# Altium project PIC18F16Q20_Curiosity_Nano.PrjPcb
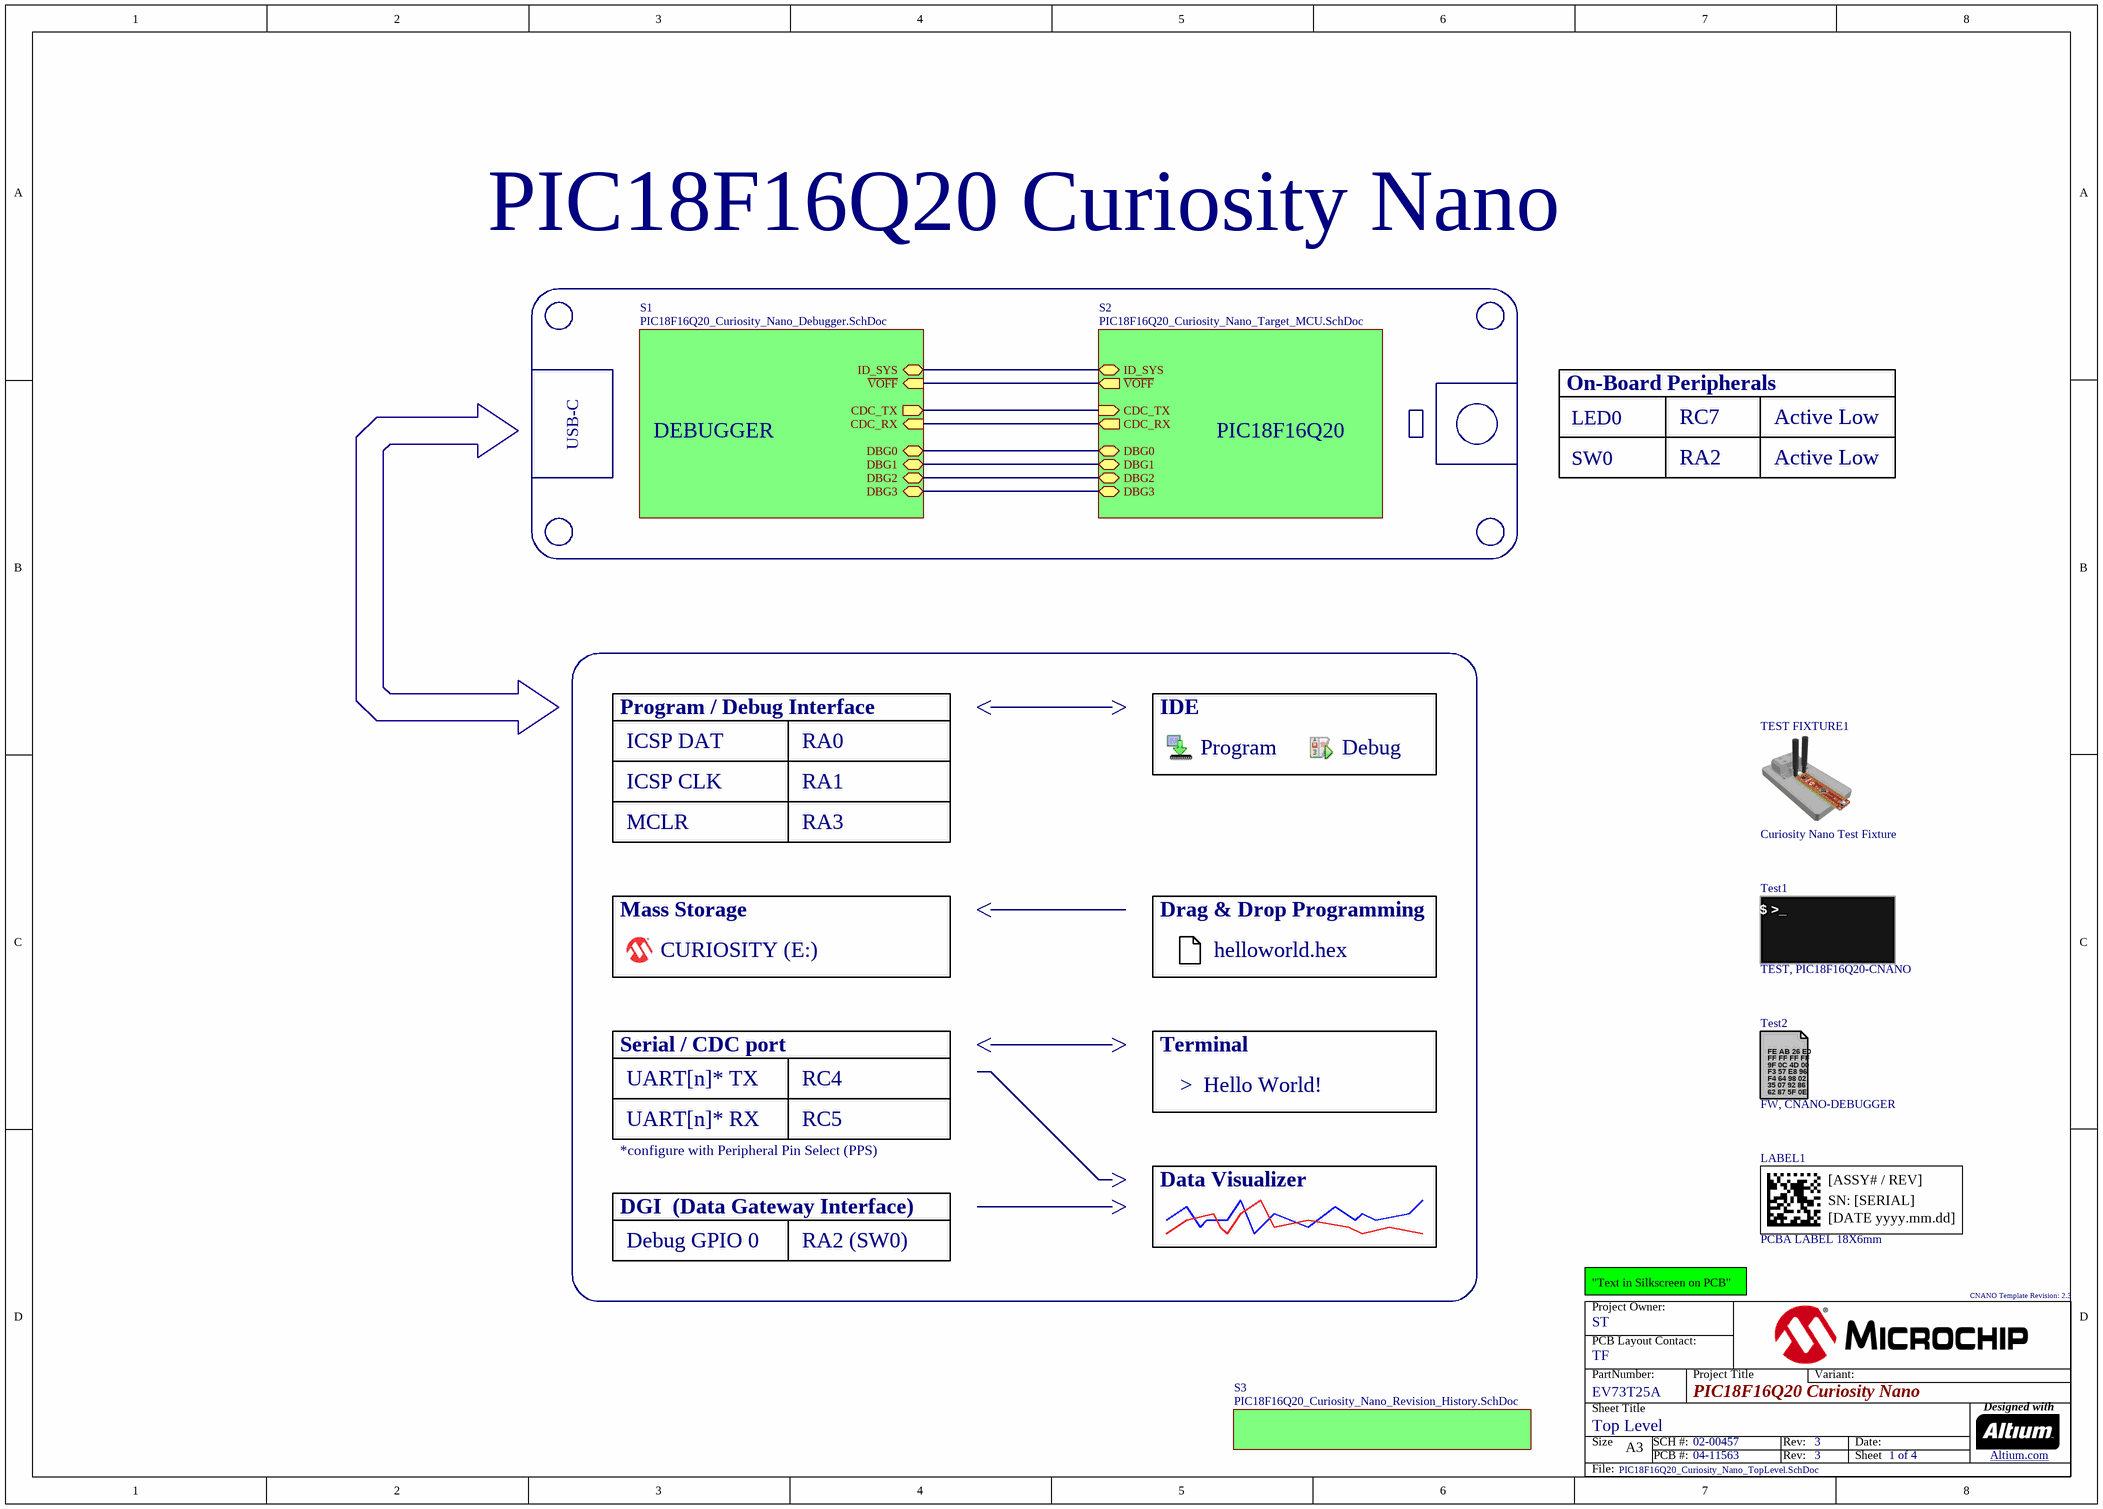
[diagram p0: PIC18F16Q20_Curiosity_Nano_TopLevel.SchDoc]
CNANO_Template_Revision: 2.3; ProjectContactOwner: ST; ProjectContactPCB: TF; ProjectContactPCBEmail: terje.frostad@microchip.com; ProjectPartNumber: EV73T25A; ProjectPCBAssyNumber: 02-00457; ProjectPCBAssyRevision: 3; ProjectPCBFabNumber: 04-11563; ProjectPCBFabRevision: 3; ProjectTargetName: PIC18F16Q20; ProjectTitle: PIC18F16Q20 Curiosity Nano
4 sheets, 80 parts. Net scope: hierarchical (ports join the sheet entries above them; power ports are global).
Board file: PIC18F16Q20_Curiosity_Nano.PcbDoc
Sheets:
  PIC18F16Q20_Curiosity_Nano_TopLevel.SchDoc
    S2 = PIC18F16Q20_Curiosity_Nano_Target_MCU.SchDoc
    S1 = PIC18F16Q20_Curiosity_Nano_Debugger.SchDoc
    S3 = PIC18F16Q20_Curiosity_Nano_Revision_History.SchDoc

## Sheet PIC18F16Q20_Curiosity_Nano_TopLevel.SchDoc
size A3; SheetTitle: Top Level; CompanyName: Microchip Technology Inc.; Organization: Microchip Technology; Address1: 2355 West Chandler Blvd.; Address2: Chandler, AZ  85224; Address4: USA; SheetNumber: 1; SheetTotal: 4

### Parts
LABEL1  value PCBA LABEL 18X6mm  [08-10015]  (hidden comment: 08-10015)
Test1  Description_: TEST, PIC18F16Q20-CNANO  (hidden comment: Mechanical)  (mechanical)
Test2  Description_: FW, CNANO-DEBUGGER  (hidden comment: Mechanical)  (mechanical)
TEST_FIXTURE1  value Curiosity Nano Test Fixture  (hidden comment: Jupiter Test Jig)  (mechanical)

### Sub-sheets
S1 = PIC18F16Q20_Curiosity_Nano_Debugger.SchDoc: DBG2 (bidir), DBG1 (bidir), DBG3 (bidir), DBG0 (bidir), ~{VOFF} (in), ID_SYS (bidir), CDC_RX (in), CDC_TX (out)
S2 = PIC18F16Q20_Curiosity_Nano_Target_MCU.SchDoc: DBG0 (bidir), DBG1 (bidir), DBG3 (bidir), DBG2 (bidir), ~{VOFF} (out), ID_SYS (bidir), CDC_RX (out), CDC_TX (in)
S3 = PIC18F16Q20_Curiosity_Nano_Revision_History.SchDoc: no entries

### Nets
CDC_RX: sheet S2/CDC_RX, sheet S1/CDC_RX
CDC_TX: sheet S2/CDC_TX, sheet S1/CDC_TX
DBG0: sheet S2/DBG0, sheet S1/DBG0
DBG1: sheet S2/DBG1, sheet S1/DBG1
DBG2: sheet S2/DBG2, sheet S1/DBG2
DBG3: sheet S2/DBG3, sheet S1/DBG3
ID_SYS: sheet S2/ID_SYS, sheet S1/ID_SYS
~{VOFF}: sheet S2/~{VOFF}, sheet S1/~{VOFF}

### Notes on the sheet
- USB-C
- DEBUGGER
- On-Board Peripherals
- LED0
- RC7
- Active Low
- SW0
- RA2
- Program / Debug Interface
- IDE
- ICSP DAT
- RA0
- Program
- Debug
- ICSP CLK
- MCLR
- RA1
- RA3
- Mass Storage
- Drag & Drop Programming
- CURIOSITY (E:)
- helloworld.hex
- Serial / CDC port
- Terminal
- UART[n]* TX
- UART[n]* RX
- RC5
- RC4
- >  Hello World!
- *configure with Peripheral Pin Select (PPS)
- Data Visualizer
- DGI  (Data Gateway Interface)
- Debug GPIO 0
- RA2 (SW0)
- "Text in Silkscreen on PCB"

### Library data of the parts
LABEL1 = 08-10015: Manufacturer 1: ACT Logimark AS; Manufacturer Part Number 1: 505462; Description_: LABEL PCBA 18x6mm Datamatrix Assy# / Rev / Serial / Date; Populated: MECH
Test1 = 13-00211: Populated: Yes
Test2 = 13-00018: Populated: Yes; Value: Debugger Firmware
TEST_FIXTURE1 = 15-00009: Manufacturer 1: Raynen; Manufacturer Part Number 1: MCHP 15-00009; Populated: YES

## Sheet PIC18F16Q20_Curiosity_Nano_Target_MCU.SchDoc
size A3; SheetTitle: Target MCU; CompanyName: Microchip Technology Inc.; Organization: Microchip Technology; Address1: 2355 West Chandler Blvd.; Address2: Chandler, AZ  85224; Address4: USA; SheetNumber: 2; SheetTotal: 4
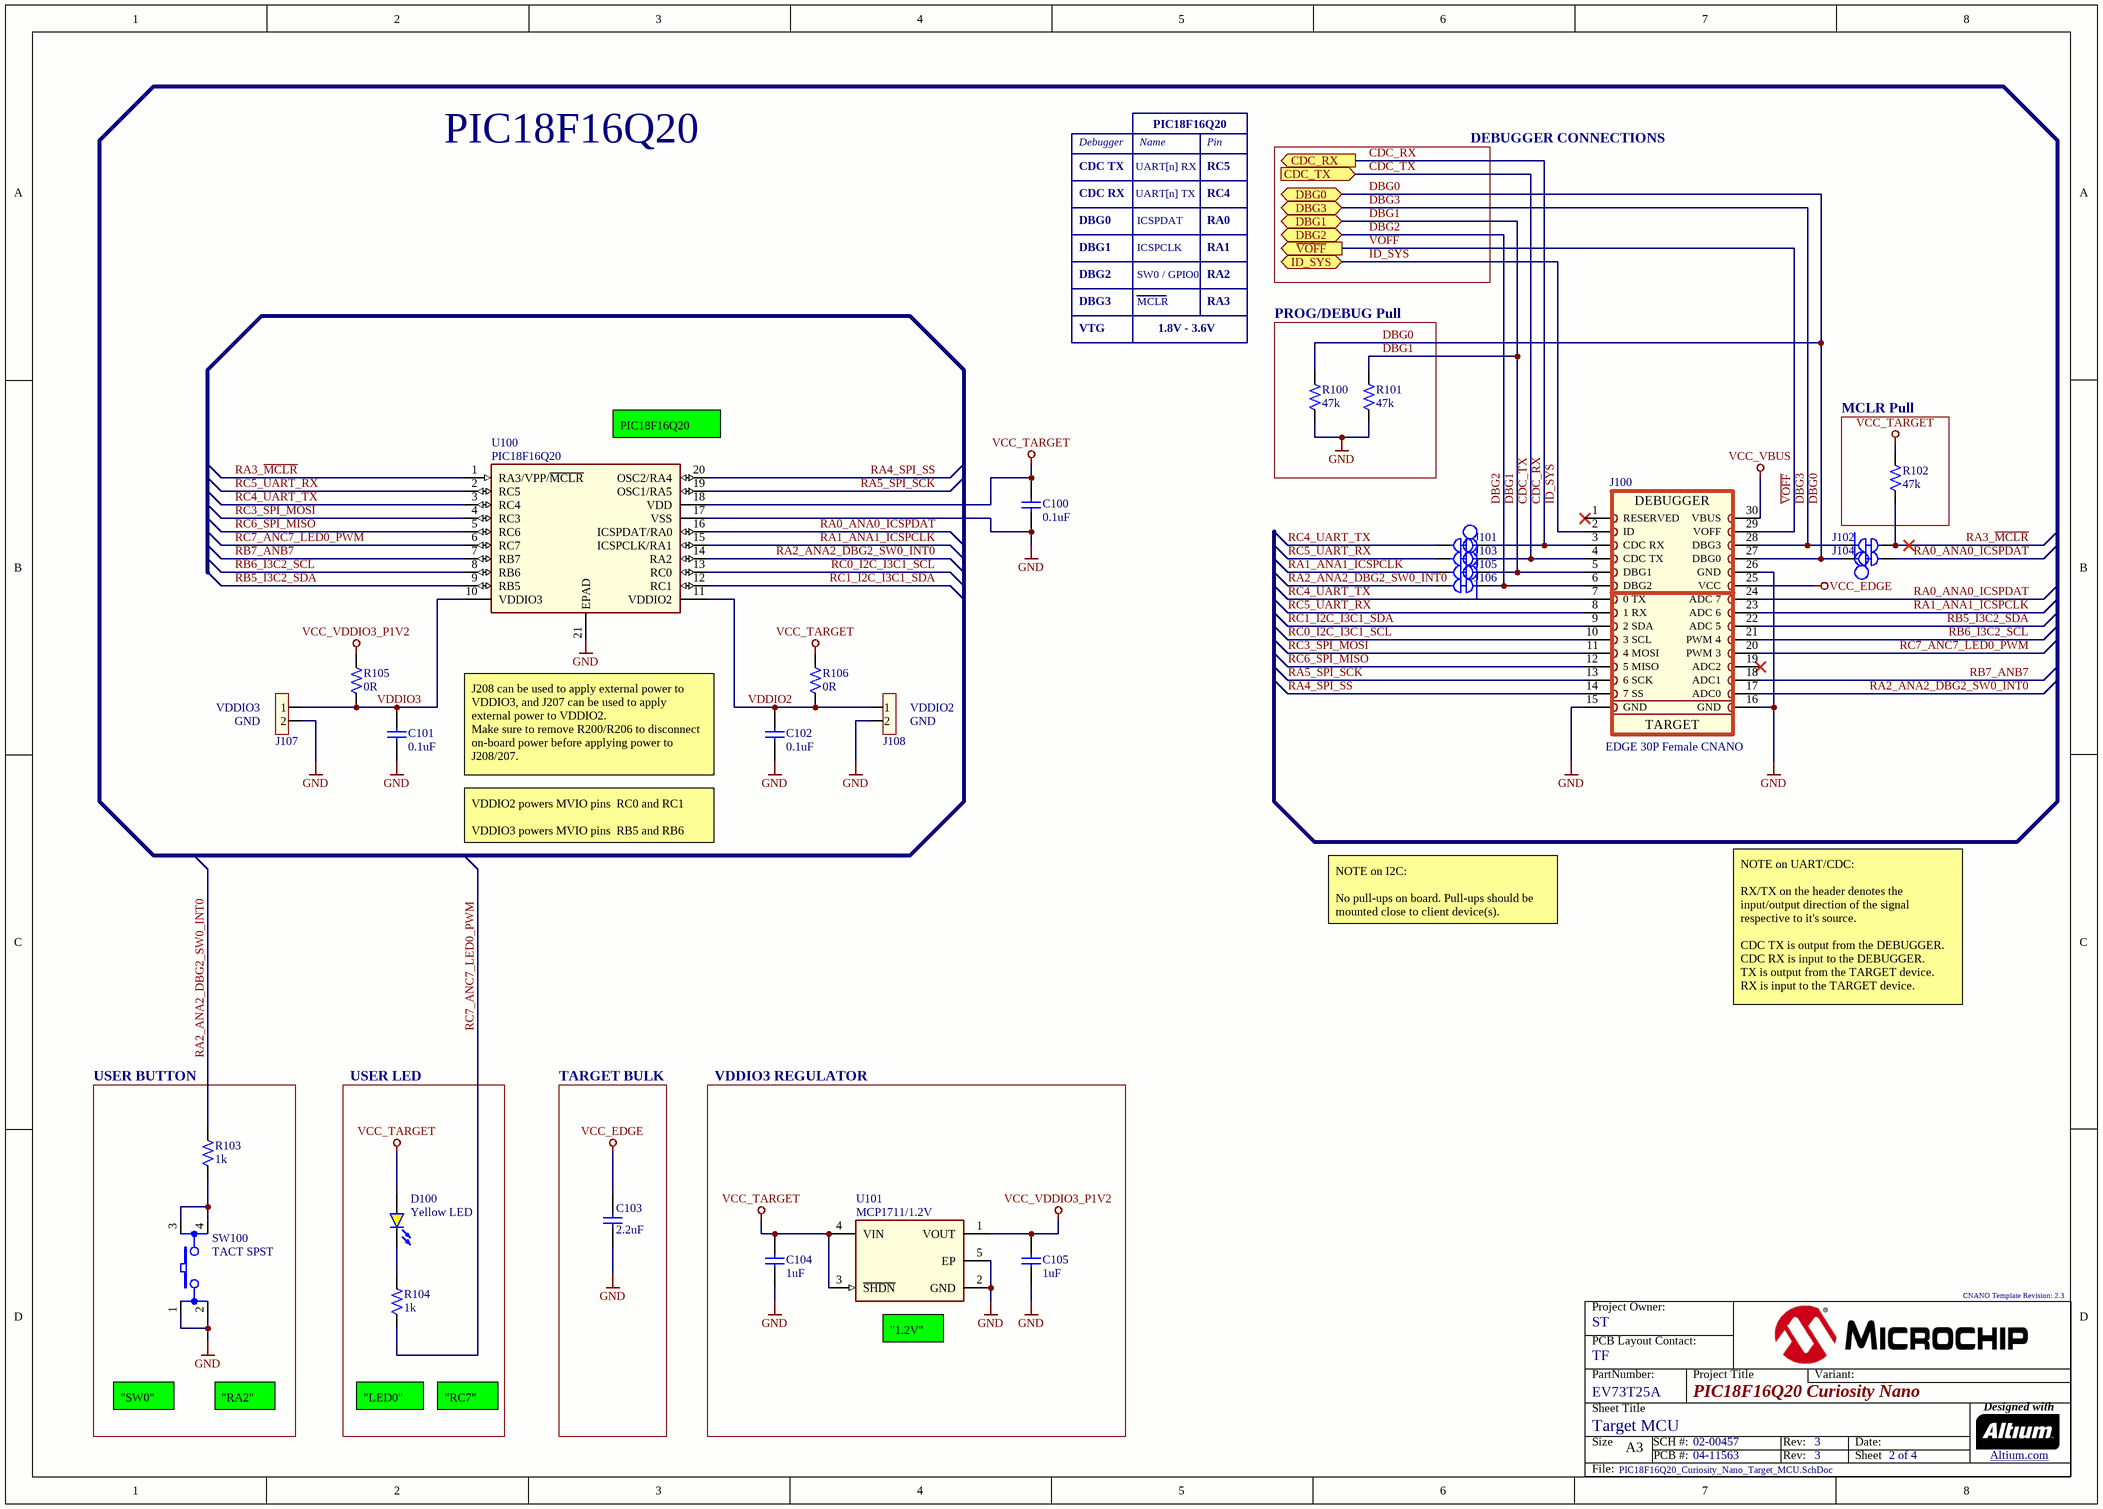
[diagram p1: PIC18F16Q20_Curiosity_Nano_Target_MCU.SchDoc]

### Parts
C100  value 0.1uF  [CAP_C_0402]  (hidden comment: Capacitor NP)
C101  value 0.1uF  [CAP_C_0402]  (hidden comment: Capacitor NP)
C102  value 0.1uF  [CAP_C_0402]  (hidden comment: Capacitor NP)
C103  value 2.2uF  [CAP_C_0402]  (hidden comment: Capacitor NP)
C104  value 1uF  [CAP_C_0402]  (hidden comment: Capacitor NP)
C105  value 1uF  [CAP_C_0402]  (hidden comment: Capacitor NP)
D100  value Yellow LED  [LED_0603_Yellow]  (hidden comment: LED_yellow)
J100  value EDGE 30P Female CNANO  [CON_EDGE_CNANO-30]  (hidden comment: CON EDGE CNANO-30)  (no BOM)
J101  CON JMPR LINK CLOSED  [CON_JMPR_0402_PCB_TRACE_LINK_0.9mm_PAD_0.6mm_PTH]  (value not drawn)  (net tie, no BOM)
J102  CON JMPR LINK CLOSED  [CON_JMPR_0402_PCB_TRACE_LINK_0.9mm_PAD_0.6mm_PTH]  (value not drawn)  (net tie, no BOM)
J103  CON JMPR LINK CLOSED  [CON_JMPR_0402_PCB_TRACE_LINK_0.9mm_PAD_0.6mm_PTH]  (value not drawn)  (net tie, no BOM)
J104  CON JMPR LINK CLOSED  [CON_JMPR_0402_PCB_TRACE_LINK_0.9mm_PAD_0.6mm_PTH]  (value not drawn)  (net tie, no BOM)
J105  CON JMPR LINK CLOSED  [CON_JMPR_0402_PCB_TRACE_LINK_0.9mm_PAD_0.6mm_PTH]  (value not drawn)  (net tie, no BOM)
J106  CON JMPR LINK CLOSED  [CON_JMPR_0402_PCB_TRACE_LINK_0.9mm_PAD_0.6mm_PTH]  (value not drawn)  (net tie, no BOM)
J107  Header 1x2  [HDR_M_2.54_1x2]  (value not drawn)
J108  Header 1x2  [HDR_M_2.54_1x2]  (value not drawn)
R100  value 47k  [RES_C_0402]  (hidden comment: Resistor)
R101  value 47k  [RES_C_0402]  (hidden comment: Resistor)
R102  value 47k  [RES_C_0402]  (hidden comment: Resistor)
R103  value 1k  [RES_C_0402]  (hidden comment: Resistor)
R104  value 1k  [RES_C_0402]  (hidden comment: Resistor)
R105  value 0R  [RES_C_0402]  (hidden comment: Resistor)
R106  value 0R  [RES_C_0402]  (hidden comment: Resistor)
SW100  value TACT SPST  [SW_TACT_SMD_KLS_L-KLS7-TS0304A-2-300-T]  (hidden comment: Switch 4 Pin)
U100  value PIC18F16Q20  [VQFN-20_3X3_EP1.8x1.8]  (hidden comment: PIC18F16Q20 T-I/REB)
U101  value MCP1711/1.2V  [UQFN-4_1x1_EP0.48x0.48]  (hidden comment: MCP1711 UQFN-4)

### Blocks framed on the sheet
PROG/DEBUG Pull: R100 R101
MCLR Pull: R102
USER BUTTON: R103 SW100
USER LED: D100 R104
TARGET BULK: C103
VDDIO3 REGULATOR: C104 C105 U101

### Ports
CDC_RX (out), CDC_TX (in), DBG0 (bidir), DBG1 (bidir), DBG2 (bidir), DBG3 (bidir), ID_SYS (bidir), ~{VOFF} (out)

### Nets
GND: C100.2 C101.2 C102.2 C103.1 C104.1 C105.1 J100.15(GND) J100.16(GND) J100.26(GND) J107.2 J108.2 R100.2 R101.2 SW100.1 SW100.2 U100.17(VSS) U100.21(EPAD) U101.2(GND) U101.5(EP)
VCC_EDGE: C103.2 J100.25(VCC)
VCC_TARGET: C100.1 C104.2 D100.1(A) R102.2 R106.2 U100.18(VDD) U101.3(~{SHDN}) U101.4(VIN)
VCC_VBUS: J100.30(VBUS)
VCC_VDDIO3_P1V2: C105.2 R105.2 U101.1(VOUT)
CDC_RX: J100.3(CDC_RX) J101.1 ; port CDC_RX
CDC_TX: J100.4(CDC_TX) J103.1 ; port CDC_TX
DBG0: J100.27(DBG0) J104.1 R100.1 ; port DBG0
DBG1: J100.5(DBG1) J105.1 R101.1 ; port DBG1
DBG2: J100.6(DBG2) J106.1 ; port DBG2
DBG3: J100.28(DBG3) J102.1 ; port DBG3
ID_SYS: J100.2(ID) ; port ID_SYS
RA0_ANA0_ICSPDAT: J100.24(ADC_7) J104.2 U100.16(ICSPDAT/RA0)
RA1_ANA1_ICSPCLK: J100.23(ADC_6) J105.2 U100.15(ICSPCLK/RA1)
RA2_ANA2_DBG2_SW0_INT0: J100.17(ADC0) J106.2 R103.1 U100.14(RA2)
RA3_~{MCLR}: J102.2 R102.1 U100.1(RA3/VPP/~{MCLR})
RA4_SPI_SS: J100.14(7_SS) U100.20(OSC2/RA4)
RA5_SPI_SCK: J100.13(6_SCK) U100.19(OSC1/RA5)
RB5_I3C2_SDA: J100.22(ADC_5) U100.9(RB5)
RB6_I3C2_SCL: J100.21(PWM_4) U100.8(RB6)
RB7_ANB7: J100.18(ADC1) U100.7(RB7)
RC0_I2C_I3C1_SCL: J100.10(3_SCL) U100.13(RC0)
RC1_I2C_I3C1_SDA: J100.9(2_SDA) U100.12(RC1)
RC3_SPI_MOSI: J100.11(4_MOSI) U100.4(RC3)
RC4_UART_TX: J100.7(0_TX) J101.2 U100.3(RC4)
RC5_UART_RX: J100.8(1_RX) J103.2 U100.2(RC5)
RC6_SPI_MISO: J100.12(5_MISO) U100.5(RC6)
RC7_ANC7_LED0_PWM: J100.20(PWM_3) R104.1 U100.6(RC7)
~{VOFF}: J100.29(VOFF) ; port ~{VOFF}
VDDIO2: C102.1 J108.1 R106.1 U100.11(VDDIO2)
VDDIO3: C101.1 J107.1 R105.1 U100.10(VDDIO3)
NetD100_2: D100.2(K) R104.2
NetR103_2: R103.2 SW100.3 SW100.4

Not connected (* = marked no-connect by the designer): J100 1(RESERVED)* 19(ADC2)*

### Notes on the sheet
- Debugger
- CDC TX
- UART[n] RX
- Name
- RC5
- Pin
- DEBUGGER CONNECTIONS
- DBG0
- CDC RX
- UART[n] TX
- ICSPDAT
- RA0
- RC4
- DBG1
- DBG2
- DBG3
- ICSPCLK
- SW0 / GPIO0
- MCLR
- RA1
- RA2
- RA3
- VTG
- 1.8V - 3.6V
- (near U100) PIC18F16Q20
- (near J107) VDDIO3
- (near J107) GND
- (near J108) GND
- (near J108) VDDIO2
- J208 can be used to apply external power to VDDIO3, and J207 can be used to apply external power to VDDIO2.
  Make sure to remove R200/R206 to disconnect on-board power before applying power to J208/207.
- VDDIO2 powers MVIO pins  RC0 and RC1
  VDDIO3 powers MVIO pins  RB5 and RB6
- NOTE on I2C:
  No pull-ups on board. Pull-ups should be mounted close to client device(s).
- NOTE on UART/CDC:
  RX/TX on the header denotes the input/output direction of the signal respective to it's source.
  CDC TX is output from the DEBUGGER.
  CDC RX is input to the DEBUGGER.
  TX is output from the TARGET device.
  RX is input to the TARGET device.
- (near U101) "1.2V"
- "SW0"
- "RA2"
- "LED0"
- "RC7"

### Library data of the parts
C100-C102 = CAP1033: Manufacturer 1: Hottech; Manufacturer Part Number 1: C1005B104K160NT; Voltage: 16V; Description_: CAP CER 0.1uF 16V 10% X7R SMD 0402; Tolerance: 10%; Type: Ceramic; Populated: Yes; Temperature Coefficient: X7R; Restricted Sourcing: No
C103 = CAP1208: Manufacturer 1: Hottech; Manufacturer Part Number 1: C1005A225K100NT; Voltage: 10V; Description_: CAP CER 2.2uF 10V 10% X5R SMD 0402; Tolerance: 10%; Type: Ceramic; Populated: YES; Temperature Coefficient: X5R; Restricted Sourcing: No
C104 C105 = CAP0616: Manufacturer 1: KEMET; Manufacturer Part Number 1: C0402C105K9PACTU; Voltage: 6.3V; Description_: CAP CER 1uF 6.3V 10% X5R SMD 0402; Tolerance: 10%; Temperature Coefficient: X5R; Type: Ceramic; Populated: Yes; Restricted Sourcing: No
D100 = DIODE1547: LED; Manufacturer 1: Rohm Semiconductor; Manufacturer Part Number 1: SML-D12Y1WT86; Description_: LED YELLOW DIFFUSED 1608 SMD; Type: LED Single; Forward Current: 20mA; Populated: YES; Restricted Sourcing: No
J100 = CON2474: Description_: CON EDGE CURIOSITY-NANO 2.54 30P Female PCB TH; Populated: MECH; Restricted Sourcing: No
J101-J106 = CON2115: Value: CON JMPR LINK CLOSED_0.9mm TH PAD; Description_: CON JUMPER 0402 CLOSED PCB TRACE LINK MANUAL CUT WITH 0.9mm TH PADS; Populated: DNP; Restricted Sourcing: No
J107 J108 = CON1632: Manufacturer 1: Würth Elektronik; Manufacturer Part Number 1: 61300211121; Value: HDR-2.54 Male 1x2; Description_: CON HDR-2.54 Male 1x2 Gold 5.84MH TH VERT; Voltage: 250V; Current: 3A; Populated: YES
R100-R102 = RES2662: Manufacturer 1: Yageo; Manufacturer Part Number 1: RC0402FR-0747KL; Tolerance: 1%; Description_: RES TKF 47k 1% 1/16W SMD 0402; Voltage: 50V; Populated: YES; Restricted Sourcing: No
R103 R104 = RES1022: Manufacturer 1: Panasonic; Manufacturer Part Number 1: ERJ-2RKF1001X; Tolerance: 1%; Description_: RES TKF 1k 1% 1/10W SMD 0402; Voltage: 50V; Power: 1/10W; Populated: YES; Temperature Coefficient: 100ppm/C
R105 R106 = RSMT1040: Manufacturer 1: Yageo; Manufacturer Part Number 1: RC0402JR-070RL; Description_: RES TKF 0R 1/16W SMD 0402; Power: 1/16W; Populated: Yes
SW100 = SWITCH1170: Switch; Manufacturer 1: KLS Electronic; Manufacturer Part Number 1: L-KLS7-TS0304A-2-300-T; Description_: SWITCH TACT SPST 12V 50mA L-KLS7-TS0304A-2-300-T SMD; Voltage: 12V; Current: 50mA; Populated: YES; Restricted Sourcing: No
U100 = MIC9477: Manufacturer 1: Microchip Technology; Description_: MCHP MCU 8-BIT 64MHz 64KB 4KB PIC18F16Q20T-I/REB VQFN-20; Populated: YES; Restricted Sourcing: No
U101 = MIC9478: LDO MCP1711; Manufacturer 1: Microchip Technology; Manufacturer Part Number 1: MCP1711T-12I/5X; Description_: MCHP ANALOG LDO 1.2V MCP1711T-12I/5X UQFN-4; Populated: YES; Restricted Sourcing: No

## Sheet PIC18F16Q20_Curiosity_Nano_Debugger.SchDoc
size A3; SheetTitle: Debugger; CompanyName: Microchip Technology Inc.; Organization: Microchip Technology; Address1: 2355 West Chandler Blvd.; Address2: Chandler, AZ  85224; Address4: USA; SheetNumber: 4; SheetTotal: 4
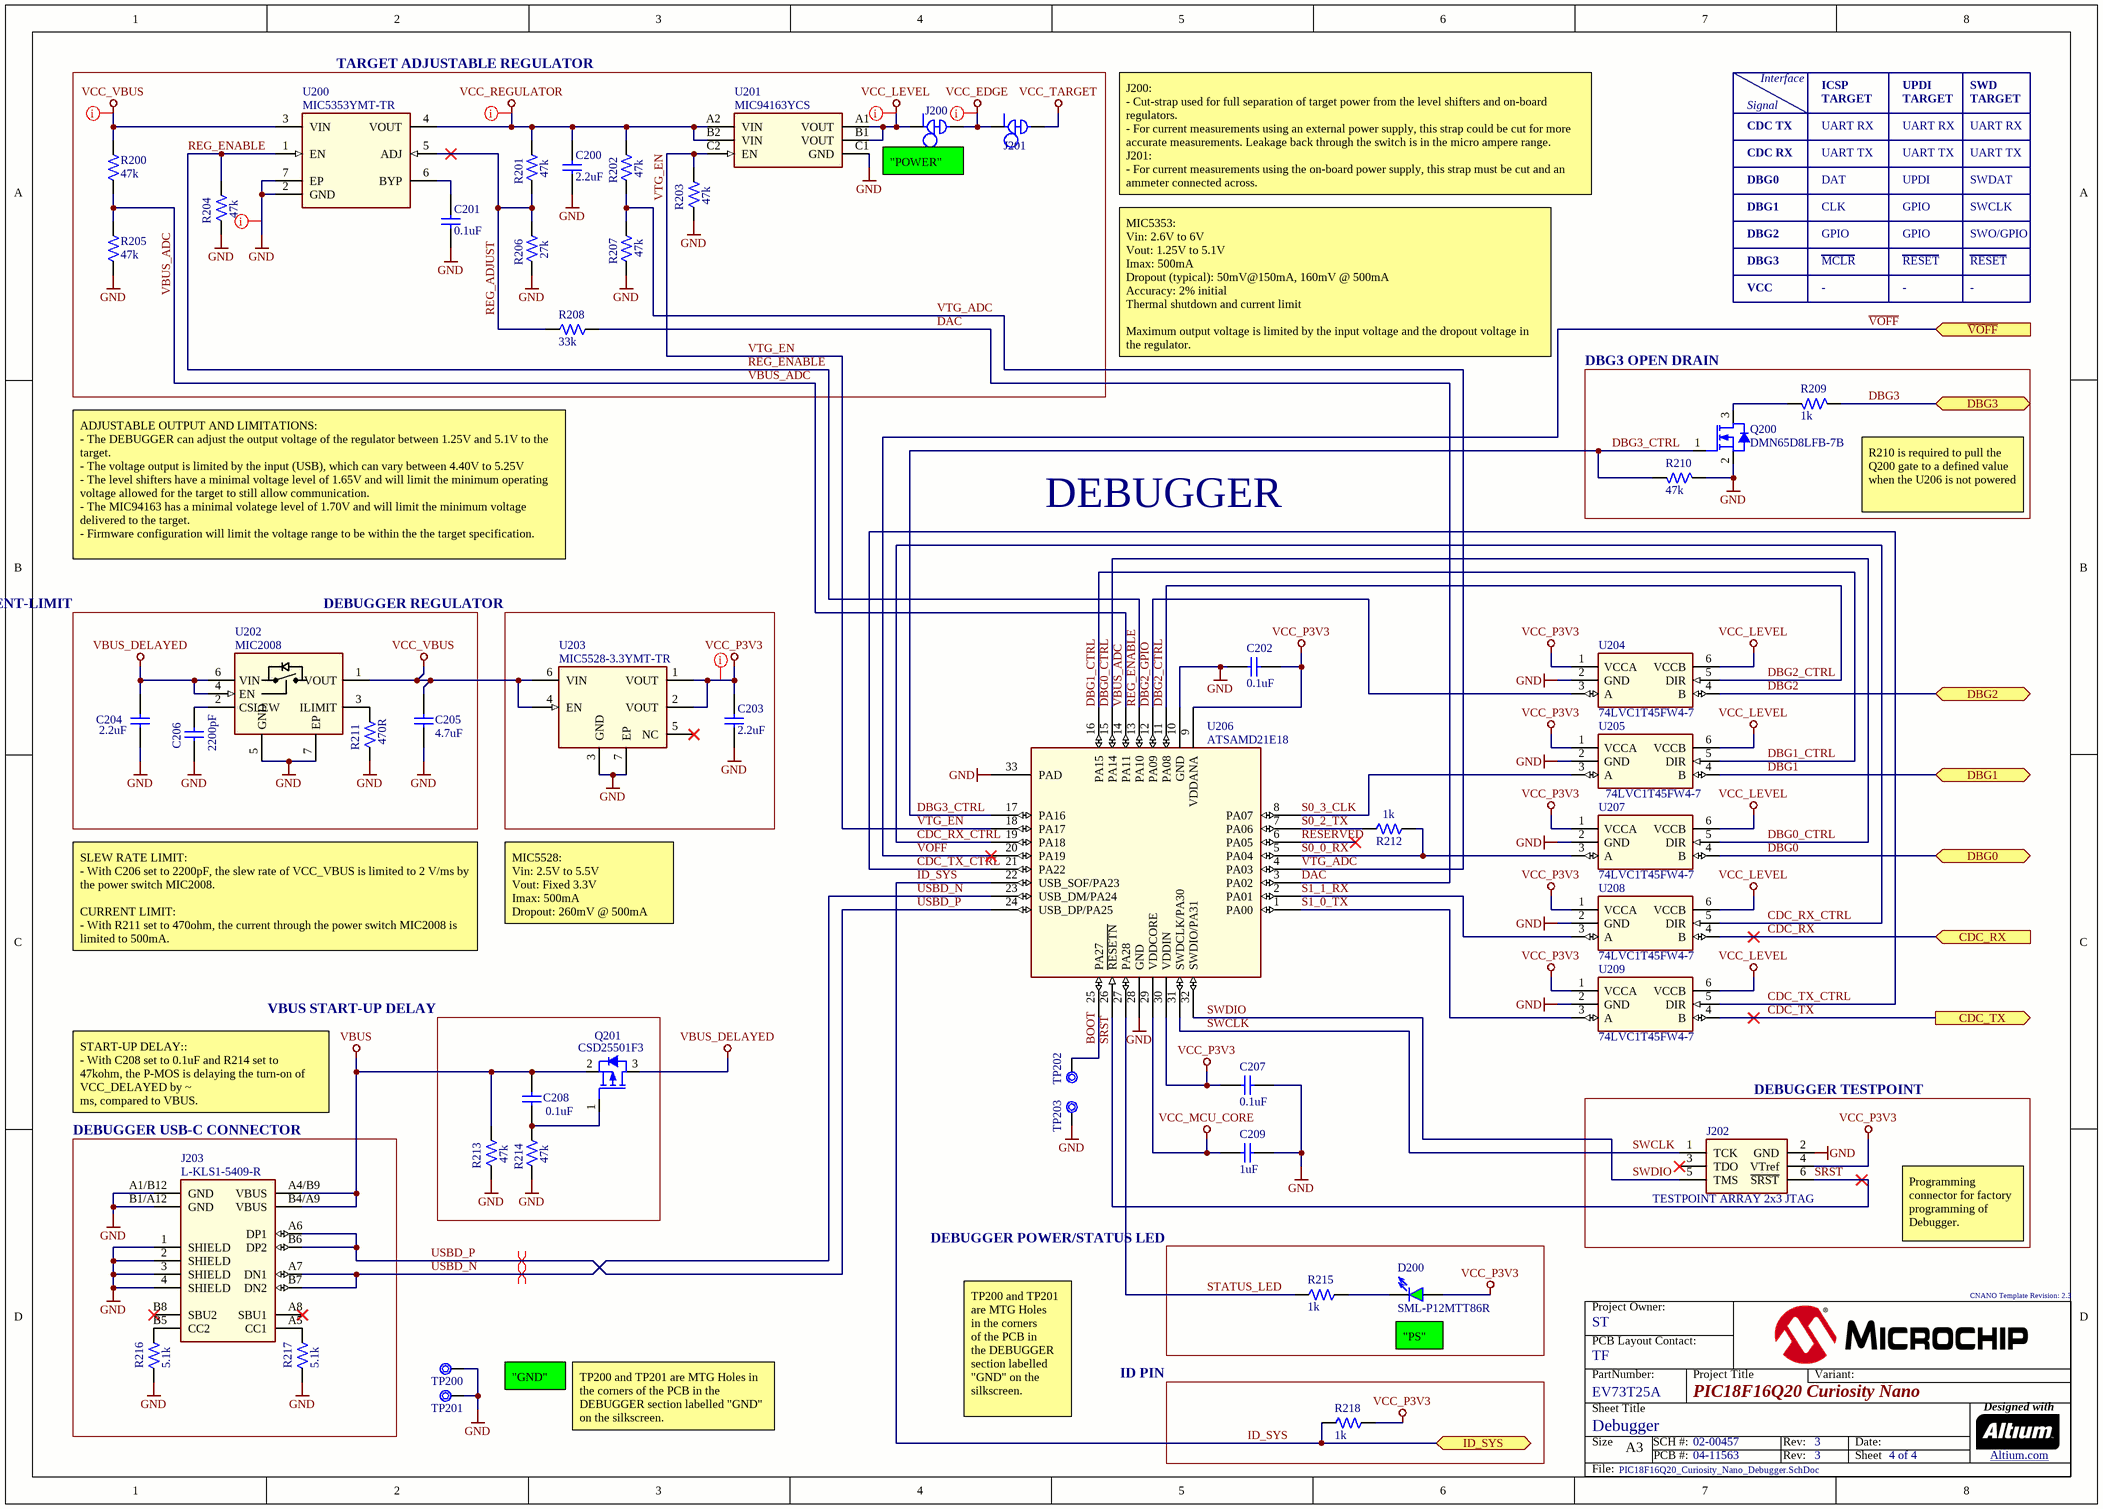
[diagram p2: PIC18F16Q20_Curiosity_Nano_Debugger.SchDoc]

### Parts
C200  value 2.2uF  [CAP_C_0402]  (hidden comment: Capacitor NP)
C201  value 0.1uF  [CAP_C_0402]  (hidden comment: Capacitor NP)
C202  value 0.1uF  [CAP_C_0402]  (hidden comment: Capacitor NP)
C203  value 2.2uF  [CAP_C_0402]  (hidden comment: Capacitor NP)
C204  value 2.2uF  [CAP_C_0402]  (hidden comment: Capacitor NP)
C205  value 4.7uF  [CAP_C_0603]  (hidden comment: Capacitor NP)
C206  value 2200pF  [CAP_C_0402]  (hidden comment: Capacitor NP)
C207  value 0.1uF  [CAP_C_0402]  (hidden comment: Capacitor NP)
C208  value 0.1uF  [CAP_C_0402]  (hidden comment: Capacitor NP)
C209  value 1uF  [CAP_C_0402]  (hidden comment: Capacitor NP)
D200  Manufacturer Part Number 1: SML-P12MTT86R  [LED_0402_GREEN]  (hidden comment: LED_green)
J200  CON JMPR LINK CLOSED  [CON_JMPR_0402_PCB_TRACE_LINK]  (value not drawn)  (net tie, no BOM)
J201  CON JMPR LINK CLOSED  [CON_JMPR_2.54_1x2_TH_PCB_TRACE_LINK]  (value not drawn)  (net tie, no BOM)
J202  value TESTPOINT ARRAY 2x3 JTAG  [TESTPOINT_ARRAY_2x3_1.27mm_pitch_SMD]  (hidden comment: TP ARRAY NO BOM)  (no BOM)
J203  Manufacturer Part Number 1: L-KLS1-5409-R  [CON_USB2.0-C_RCPT_SMD_RA_KLS_KLS1-5409]  (hidden comment: CON USB2.0-C RCPT SMD RA KLS KLS1-5409)
Q200  value DMN65D8LFB-7B  [X1-DFN1006-3]  (hidden comment: Transistor MOS-N GSD)
Q201  value CSD25501F3  [LGA-3_GSD_0.7x0.6_CSD25501F3]  (hidden comment: Transistor MOS-P GSD)
R200  value 47k  [RES_C_0402]  (hidden comment: Resistor)
R201  value 47k  [RES_C_0402]  (hidden comment: Resistor)
R202  value 47k  [RES_C_0402]  (hidden comment: Resistor)
R203  value 47k  [RES_C_0402]  (hidden comment: Resistor)
R204  value 47k  [RES_C_0402]  (hidden comment: Resistor)
R205  value 47k  [RES_C_0402]  (hidden comment: Resistor)
R206  value 27k  [RES_C_0402]  (hidden comment: Resistor)
R207  value 47k  [RES_C_0402]  (hidden comment: Resistor)
R208  value 33k  [RES_C_0402]  (hidden comment: Resistor)
R209  value 1k  [RES_C_0402]  (hidden comment: Resistor)
R210  value 47k  [RES_C_0402]  (hidden comment: Resistor)
R211  value 470R  [RES_C_0402]  (hidden comment: Resistor)
R212  value 1k  [RES_C_0402]  (hidden comment: Resistor)
R213  value 47k  [RES_C_0402]  (hidden comment: Resistor)
R214  value 47k  [RES_C_0402]  (hidden comment: Resistor)
R215  value 1k  [RES_C_0402]  (hidden comment: Resistor)
R216  value 5.1k  [RES_C_0402]  (hidden comment: Resistor)
R217  value 5.1k  [RES_C_0402]  (hidden comment: Resistor)
R218  value 1k  [RES_C_0402]  (hidden comment: Resistor)
TP200  Test Point No BOM  [TP_3.6X2.7]  (value not drawn)  (no BOM)
TP201  Test Point No BOM  [TP_3.6X2.7]  (value not drawn)  (no BOM)
TP202  Test Point No BOM  [CON_TP_0.8dia_SMD_with_Test_Jig_Layer]  (value not drawn)  (no BOM)
TP203  Test Point No BOM  [CON_TP_0.8dia_SMD_with_Test_Jig_Layer]  (value not drawn)  (no BOM)
U200  value MIC5353YMT-TR  [MLF-6 1.6X1.6mm]  (hidden comment: MIC53XX ADJ MLF-6)
U201  value MIC94163YCS  [MIC94163_1.5MM_1MM]  (hidden comment: MIC94163_1.5MM_1MM)
U202  value MIC2008  [VDFN-6_2x2_EP0.8X1.40]  (hidden comment: MIC2008YML-TR VDFN-6)
U203  Manufacturer Part Number 1: MIC5528-3.3YMT-TR  [DFN-6_1.2x1.2]  (hidden comment: MIC5528MT DFN-6)
U204  value 74LVC1T45FW4-7  [X2-DFN1010-6]  (hidden comment: 74LVC(H)1T45 SOT-23-6_SC-70-6_SOT-6_SOT-363_DSBGA)
U205  value 74LVC1T45FW4-7  [X2-DFN1010-6]  (hidden comment: 74LVC(H)1T45 SOT-23-6_SC-70-6_SOT-6_SOT-363_DSBGA)
U206  value ATSAMD21E18  [QFN-32_5X5_EP3.6x3.6_L]  (hidden comment: SAMD21E QFN-32)
U207  value 74LVC1T45FW4-7  [X2-DFN1010-6]  (hidden comment: 74LVC(H)1T45 SOT-23-6_SC-70-6_SOT-6_SOT-363_DSBGA)
U208  value 74LVC1T45FW4-7  [X2-DFN1010-6]  (hidden comment: 74LVC(H)1T45 SOT-23-6_SC-70-6_SOT-6_SOT-363_DSBGA)
U209  value 74LVC1T45FW4-7  [X2-DFN1010-6]  (hidden comment: 74LVC(H)1T45 SOT-23-6_SC-70-6_SOT-6_SOT-363_DSBGA)

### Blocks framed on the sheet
TARGET ADJUSTABLE REGULATOR: C200 C201 J200 J201 R200-R208 U200 U201
DBG3 OPEN DRAIN: Q200 R209 R210
VBUS SLEW RATE- & CURRENT-LIMIT: C204-C206 R211 U202
DEBUGGER REGULATOR: C203 U203
VBUS START-UP DELAY: C208 Q201 R213 R214
DEBUGGER TESTPOINT: J202
DEBUGGER USB-C CONNECTOR: J203 R216 R217
DEBUGGER POWER/STATUS LED: D200 R215
ID PIN: R218

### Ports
CDC_RX (in), CDC_TX (out), DBG0 (bidir), DBG1 (bidir), DBG2 (bidir), DBG3 (bidir), ID_SYS (bidir), ~{VOFF} (in)

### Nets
GND: C200.1 C201.2 C202.1 C203.1 C204.1 C205.1 C206.1 C207.2 C209.1 J202.2(GND) J203.1(SHIELD) J203.2(SHIELD) J203.3(SHIELD) J203.4(SHIELD) J203.A1/B12(GND) J203.B1/A12(GND) Q200.2(S) R203.2 R204.2 R205.1 R206.1 R207.1 R210.2 R211.2 R213.2 R214.2 R216.2 R217.2 TP200.1 TP201.1 TP203.1 U200.2(GND) U200.7(EP) U201.C1(GND) U202.5(GND) U202.7(EP) U203.3(GND) U203.7(EP) U204.2(GND) U205.2(GND) U206.10(GND) U206.28(GND) U206.33(PAD) U207.2(GND) U208.2(GND) U209.2(GND)
VBUS: C208.2 J203.A4/B9(VBUS) J203.B4/A9(VBUS) Q201.2(S) R213.1
VBUS_DELAYED: C204.2 Q201.3(D) U202.4(EN) U202.6(VIN)
VCC_EDGE: J200.2 J201.1
VCC_LEVEL: J200.1 U201.A1(VOUT) U201.B1(VOUT) U204.6(VCCB) U205.6(VCCB) U207.6(VCCB) U208.6(VCCB) U209.6(VCCB)
VCC_MCU_CORE: C209.2 U206.29(VDDCORE)
VCC_P3V3: C202.2 C203.2 C207.1 D200.1(A) J202.4(VTref) R218.2 U203.1(VOUT) U203.2(VOUT) U204.1(VCCA) U205.1(VCCA) U206.9(VDDANA) U206.30(VDDIN) U207.1(VCCA) U208.1(VCCA) U209.1(VCCA)
VCC_REGULATOR: C200.2 R201.1 R202.2 U200.4(VOUT) U201.A2(VIN) U201.B2(VIN)
VCC_TARGET: J201.2
VCC_VBUS: C205.2 R200.1 U200.3(VIN) U202.1(VOUT) U203.4(EN) U203.6(VIN)
BOOT: TP202.1 U206.25(PA27)
CDC_RX: U208.4(B) ; port CDC_RX
CDC_RX_CTRL: U206.19(PA18) U208.5(DIR)
CDC_TX: U209.4(B) ; port CDC_TX
CDC_TX_CTRL: U206.21(PA22) U209.5(DIR)
DAC: R208.2 U206.3(PA02)
DBG0: U207.4(B) ; port DBG0
DBG0_CTRL: U206.15(PA14) U207.5(DIR)
DBG1: U205.4(B) ; port DBG1
DBG1_CTRL: U205.5(DIR) U206.16(PA15)
DBG2: U204.4(B) ; port DBG2
DBG2_CTRL: U204.5(DIR) U206.11(PA08)
DBG2_GPIO: U204.3(A) U206.12(PA09)
DBG3: R209.2 ; port DBG3
DBG3_CTRL: Q200.1(G) R210.1 U206.17(PA16)
ID_SYS: R218.1 U206.22(USB_SOF/PA23) ; port ID_SYS
REG_ADJUST: R201.2 R206.2 R208.1 U200.5(ADJ)
REG_ENABLE: R204.1 U200.1(EN) U206.13(PA10)
RESERVED: U206.6(PA05)
S0_0_RX: R212.1 U206.5(PA04) U207.3(A)
S0_2_TX: R212.2 U206.7(PA06)
S0_3_CLK: U205.3(A) U206.8(PA07)
S1_0_TX: U206.1(PA00) U209.3(A)
S1_1_RX: U206.2(PA01) U208.3(A)
~{SRST}: J202.6(~{SRST}) U206.26(~{RESETN})
STATUS_LED: R215.2 U206.27(PA28)
SWCLK: J202.1(TCK) U206.31(SWDCLK/PA30)
SWDIO: J202.5(TMS) U206.32(SWDIO/PA31)
USBD_N: J203.A7(DN1) J203.B7(DN2) U206.23(USB_DM/PA24)
USBD_P: J203.A6(DP1) J203.B6(DP2) U206.24(USB_DP/PA25)
~{VOFF}: U206.20(PA19) ; port ~{VOFF}
VBUS_ADC: R200.2 R205.2 U206.14(PA11)
VTG_ADC: R202.1 R207.2 U206.4(PA03)
VTG_EN: R203.1 U201.C2(EN) U206.18(PA17)
NetC201_1: C201.1 U200.6(BYP)
NetC206_2: C206.2 U202.2(CSLEW)
NetC208_1: C208.1 Q201.1(G) R214.1
NetD200_2: D200.2(K) R215.1
NetJ203_A5: J203.A5(CC1) R217.1
NetJ203_B5: J203.B5(CC2) R216.1
NetQ200_3: Q200.3(D) R209.1
NetR211_1: R211.1 U202.3(ILIMIT)

Not connected (* = marked no-connect by the designer): J202 3(TDO)*; J203 A8(SBU1)* B8(SBU2)*; U203 5(NC)*

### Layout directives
net class Power: GND, VCC_EDGE, VCC_LEVEL, VCC_P3V3, VCC_REGULATOR, VCC_VBUS
differential pair: USBD_N, USBD_P

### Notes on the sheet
- Signal
- Interface
- ICSP
- TARGET
- UPDI
- SWD
- (near J200) "POWER"
- CDC TX
- CDC RX
- DBG0
- UART RX
- UART TX
- DAT
- SWDAT
- J200:
  - Cut-strap used for full separation of target power from the level shifters and on-board regulators.
  - For current measurements using an external power supply, this strap could be cut for more accurate measurements. Leakage back through the switch is in the micro ampere range.
  J201:
  - For current measurements using the on-board power supply, this strap must be cut and an ammeter connected across.
- DBG1
- DBG2
- CLK
- GPIO
- SWCLK
- SWO/GPIO
- DBG3
- VCC
- MCLR
- -
- RESET
- MIC5353:
  Vin: 2.6V to 6V
  Vout: 1.25V to 5.1V
  Imax: 500mA
  Dropout (typical): 50mV@150mA, 160mV @ 500mA
  Accuracy: 2% initial
  Thermal shutdown and current limit
  Maximum output voltage is limited by the input voltage and the dropout voltage in the regulator.
  (Vmax = Vin - dropout)
- DEBUGGER
- (near R209) R210 is required to pull the Q200 gate to a defined value when the U206 is not powered
- ADJUSTABLE OUTPUT AND LIMITATIONS:
  - The DEBUGGER can adjust the output voltage of the regulator between 1.25V and 5.1V to the target.
  - The voltage output is limited by the input (USB), which can vary between 4.40V to 5.25V
  - The level shifters have a minimal voltage level of 1.65V and will limit the minimum operating voltage allowed for the target to still allow communication.
  - The MIC94163 has a minimal volatege level of 1.70V and will limit the minimum voltage delivered to the target.
  - Firmware configuration will limit the voltage range to be within the the target specification.
- MIC5528:
  Vin: 2.5V to 5.5V
  Vout: Fixed 3.3V
  Imax: 500mA
  Dropout: 260mV @ 500mA
- SLEW RATE LIMIT:
  - With C206 set to 2200pF, the slew rate of VCC_VBUS is limited to 2 V/ms by the power switch MIC2008.
  CURRENT LIMIT:
  - With R211 set to 470ohm, the current through the power switch MIC2008 is limited to 500mA.
- START-UP DELAY::
  - With C208 set to 0.1uF and R214 set to 47kohm, the P-MOS is delaying the turn-on of VCC_DELAYED by ~
  ms, compared to VBUS.
- Programming connector for factory programming of Debugger.
- "GND"
- (near D200) "PS"
- TP200 and TP201 are MTG Holes in the corners of the PCB in the DEBUGGER section labelled "GND" on the silkscreen.
- TP200 and TP201
  are MTG Holes
  in the corners
  of the PCB in
  the DEBUGGER
  section labelled
  "GND" on the
  silkscreen.

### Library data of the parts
C200 C203 C204 = CAP1208: as C103 on sheet PIC18F16Q20_Curiosity_Nano_Target_MCU
C201 C202 C207 C208 = CAP1033: as C100 on sheet PIC18F16Q20_Curiosity_Nano_Target_MCU
C205 = CAP0543: Manufacturer 1: KEMET; Manufacturer Part Number 1: C0603C475K8PACTU; Voltage: 10V; Description_: CAP CER 4.7uF 10V 10% X5R SMD 0603; Tolerance: 10%; Type: Ceramic; Populated: Yes; Temperature Coefficient: X5R; Restricted Sourcing: No
C206 = CAP1265: Manufacturer 1: KEMET; Manufacturer Part Number 1: C0402C222J3GACTU; Voltage: 25V; Description_: CAP CER 2200pF 25V 5% C0G SMD 0402; Tolerance: 5%; Type: Ceramic; Populated: YES; Temperature Coefficient: C0G; Restricted Sourcing: No
C209 = CAP0616: Manufacturer 1: KEMET; Manufacturer Part Number 1: C0402C105K9PACTU; Voltage: 6.3V; Description_: CAP CER 1uF 6.3V 10% X5R SMD 0402; Tolerance: 10%; Type: Ceramic; Populated: Yes; Temperature Coefficient: X5R; Restricted Sourcing: No
D200 = LED1092: LED; Manufacturer 1: Rohm Semiconductor; Value: LED SINGLE SML-P12MTT86R YELLOW-GREEN; Description_: DIO LED YELLOW-GREEN 2.2V 20mA 25mcd Clear SMD 0402; Type: LED Single; Forward Current: 20mA; Power: 54mW; Reverse Current: 10uA; Reverse Voltage: 5V; Populated: YES; Restricted Sourcing: No
J200 = CON2116: Value: CON 0402 PCB TRACE LINK; Description_: CON JUMPER 0402 CLOSED PCB TRACE LINK MANUAL CUT; Populated: DNP; Restricted Sourcing: No
J201 = CON2118: Value: CON JMPR 1x2 PCB TRACE LINK; Description_: CON JUMPER-2.54 1x2 PCB TRACE LINK MANUAL CUT; Populated: DNP; Restricted Sourcing: No
J202 = CON2119: Description_: CON TP ARRAY 2x3 1.27mm pitch JTAG; Populated: DNP
J203 = CON2580: Manufacturer 1: KLS Electronic; Value: USB2.0 Type-C FEMALE; Description_: CON USB2.0 Type-C Female SMD R/A; Voltage: 100V AC; Current: 5A; Populated: YES; Restricted Sourcing: No
Q200 = TRA1340: Transistor MOS; Manufacturer 1: Diodes Incorporated; Manufacturer Part Number 1: DMN65D8LFB-7; Description_: TRANS FET N-CH DMN65D8LFB-7B 260mA 60V 430mW X1_DFN1006-3; Type: FET; Current: 260mA; Drain to Source Voltage: 60V; Power: 430mW; Populated: YES; Restricted Sourcing: No
Q201 = TRA1611: Transistor MOS; Manufacturer 1: Texas Instruments; Description_: TRANS FET P-CH CSD25501F3 -20V -3.6A 0.076R LGA; Type: FET; Current: -3.6A; Drain to Source Voltage: -20V; Populated: YES; Restricted Sourcing: No
R200-R205 R207 R210 R213 R214 = RES2662: as R100 on sheet PIC18F16Q20_Curiosity_Nano_Target_MCU
R206 = RES2661: Manufacturer 1: Yageo; Manufacturer Part Number 1: RC0402FR-0727KL; Tolerance: 1%; Description_: RES TKF 27k 1% 1/16W SMD 0402; Populated: YES; Voltage: 50V; Restricted Sourcing: No
R208 = RES1994: Manufacturer 1: Yageo; Manufacturer Part Number 1: AC0402FR-0733KL; Tolerance: 1%; Description_: RES TKF 33k 1% 1/16W SMD 0402; Power: 1/16W; Populated: YES; Temperature Coefficient: 100ppm/C; Restricted Sourcing: No
R209 R212 R215 R218 = RES1022: as R103 on sheet PIC18F16Q20_Curiosity_Nano_Target_MCU
R211 = RSMT1163: Manufacturer 1: Yageo; Manufacturer Part Number 1: RC0402FR-07470RL; Tolerance: 1%; Description_: RES TKF 470R 1% 1/16W MF 0402; Populated: YES; Restricted Sourcing: No
R216 R217 = RES1655: Manufacturer 1: Panasonic Electronic Components; Manufacturer Part Number 1: ERJ-2RKF5101X; Tolerance: 1%; Description_: RES TKF 5.1k 1% 1/10W SMD 0402; Temperature Coefficient: 100ppm/C; Power: 1/10W; Populated: YES
TP200 TP201 = CON2131: Test Point; Value: TP TH D3.6H2.7; Description_: CON TP PAD PCB TH D3.6H2.7; Populated: Yes
TP202 TP203 = CON2120: Test Point; Value: TP SMD D0.8; Description_: CON TP PAD PCB SMD D0.8; Populated: DNP
U200 = MIC7389: LDO Regulator; Manufacturer 1: Microchip Technology; Description_: MCHP ANALOG LDO ADJ 500mA MIC5353YMT-TR MLF-6; Populated: YES; Restricted Sourcing: No
U201 = MIC8744: Manufacturer 1: Microchip Technology; Manufacturer Part Number 1: MIC94163YCS-TR; Description_: IC LOAD SWITCH HI SIDE 3A 6WLCSP; Populated: YES; Restricted Sourcing: No
U202 = MIC9604: Manufacturer 1: Microchip Technology; Description_: MCHP ANALOG POWER SWITCH 5.5V 2.1A MIC2008YML-TR VDFN-6; Populated: YES; Restricted Sourcing: No
U203 = MIC6905: Manufacturer 1: Microchip Technology; Value: MIC5528 3V3; Description_: MCHP ANALOG LDO 3.3V MIC5528-3.3YMT-TR 6-TDFN; Populated: YES
U204 U205 U207-U209 = IC1665: Manufacturer 1: Diodes Incorporated; MCHP-ID: IC1665; Description_: IC VOLTAGE TRANSLATOR BI-DIR 1 CIRCUIT 74LVC1T45FW4-7 X2-DFN1010-6; Populated: YES; Restricted Sourcing: No
U206 = MIC8641: Manufacturer 1: Microchip Technology; Manufacturer Part Number 1: ATSAMD21E18A-MUT; Description_: MCHP MCU 32-BIT 48MHz 256Kb 32Kb ATSAMD21E18A-MUT QFN-32; Populated: YES; Restricted Sourcing: No

## Sheet PIC18F16Q20_Curiosity_Nano_Revision_History.SchDoc
size A3; SheetTitle: Revision History; CompanyName: Microchip Technology Inc.; Organization: Microchip Technology; Address1: 2355 West Chandler Blvd.; Address2: Chandler, AZ  85224; Address4: USA; SheetNumber: 4; SheetTotal: 3
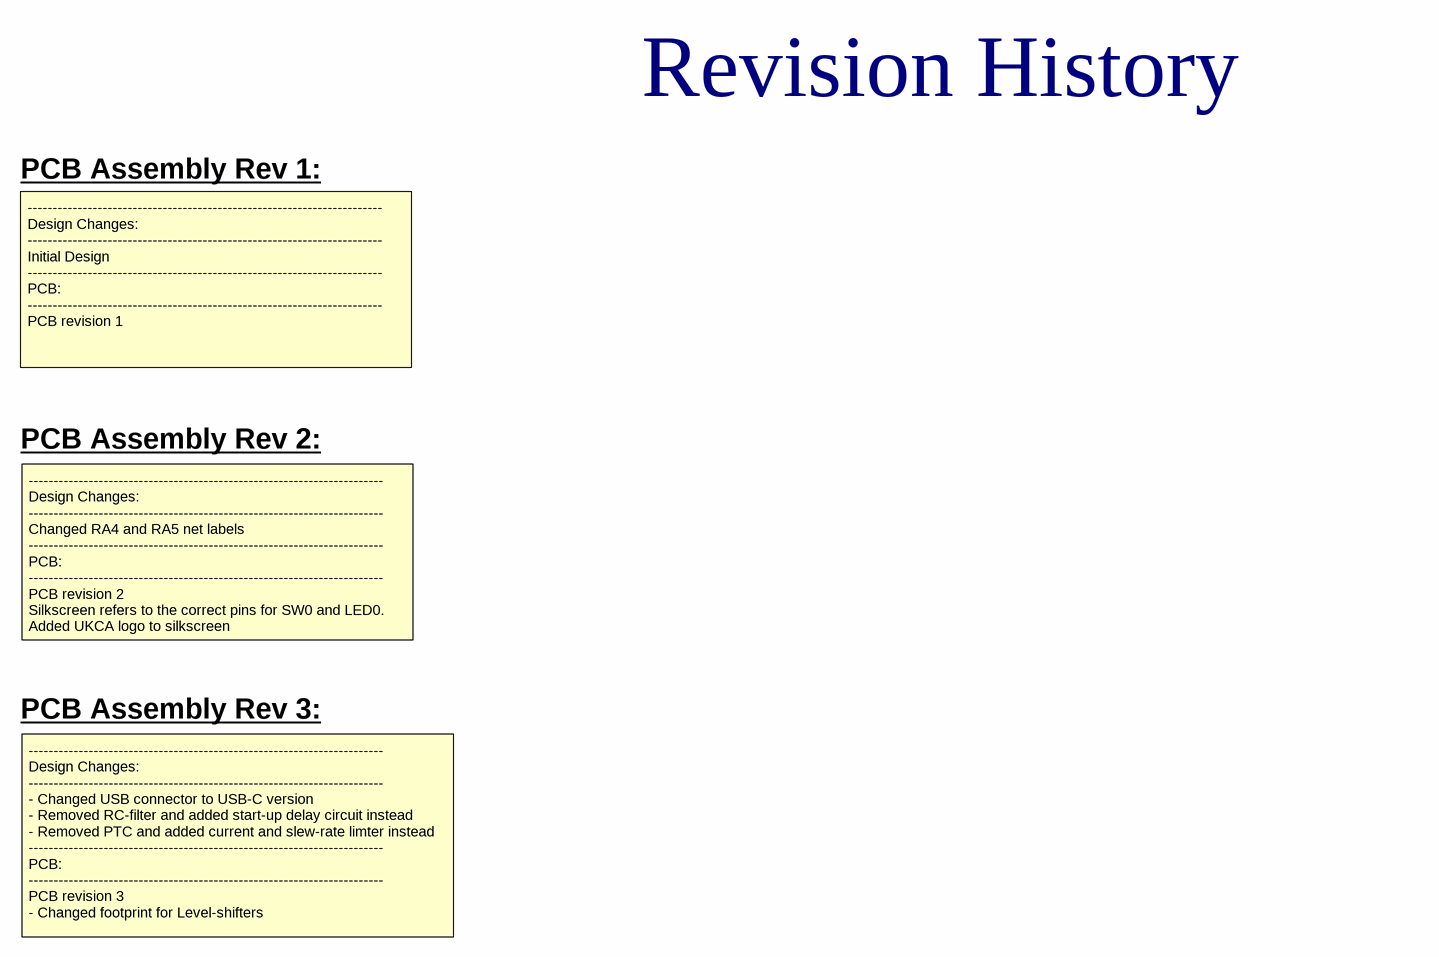
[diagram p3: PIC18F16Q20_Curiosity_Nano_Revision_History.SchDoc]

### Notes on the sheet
- Revision History
- PCB Assembly Rev 1:
- -----------------------------------------------------------------------
  Design Changes:
  -----------------------------------------------------------------------
  Initial Design
  -----------------------------------------------------------------------
  PCB:
  -----------------------------------------------------------------------
  PCB revision 1
- PCB Assembly Rev 2:
- -----------------------------------------------------------------------
  Design Changes:
  -----------------------------------------------------------------------
  Changed RA4 and RA5 net labels
  -----------------------------------------------------------------------
  PCB:
  -----------------------------------------------------------------------
  PCB revision 2
  Silkscreen refers to the correct pins for SW0 and LED0. Added UKCA logo to silkscreen
- PCB Assembly Rev 3:
- -----------------------------------------------------------------------
  Design Changes:
  -----------------------------------------------------------------------
  - Changed USB connector to USB-C version
  - Removed RC-filter and added start-up delay circuit instead
  - Removed PTC and added current and slew-rate limter instead
  -----------------------------------------------------------------------
  PCB:
  -----------------------------------------------------------------------
  PCB revision 3
  - Changed footprint for Level-shifters

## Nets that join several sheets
GND: PIC18F16Q20_Curiosity_Nano_Target_MCU (19 pins), PIC18F16Q20_Curiosity_Nano_Debugger (46 pins)
VCC_EDGE: PIC18F16Q20_Curiosity_Nano_Target_MCU (C103.2 J100.25), PIC18F16Q20_Curiosity_Nano_Debugger (J200.2 J201.1)
VCC_TARGET: PIC18F16Q20_Curiosity_Nano_Target_MCU (8 pins), PIC18F16Q20_Curiosity_Nano_Debugger (J201.2)
VCC_VBUS: PIC18F16Q20_Curiosity_Nano_Target_MCU (J100.30), PIC18F16Q20_Curiosity_Nano_Debugger (6 pins)
CDC_RX: PIC18F16Q20_Curiosity_Nano_Target_MCU (J100.3 J101.1), PIC18F16Q20_Curiosity_Nano_Debugger (U208.4)
CDC_TX: PIC18F16Q20_Curiosity_Nano_Target_MCU (J100.4 J103.1), PIC18F16Q20_Curiosity_Nano_Debugger (U209.4)
DBG0: PIC18F16Q20_Curiosity_Nano_Target_MCU (J100.27 J104.1 R100.1), PIC18F16Q20_Curiosity_Nano_Debugger (U207.4)
DBG1: PIC18F16Q20_Curiosity_Nano_Target_MCU (J100.5 J105.1 R101.1), PIC18F16Q20_Curiosity_Nano_Debugger (U205.4)
DBG2: PIC18F16Q20_Curiosity_Nano_Target_MCU (J100.6 J106.1), PIC18F16Q20_Curiosity_Nano_Debugger (U204.4)
DBG3: PIC18F16Q20_Curiosity_Nano_Target_MCU (J100.28 J102.1), PIC18F16Q20_Curiosity_Nano_Debugger (R209.2)
ID_SYS: PIC18F16Q20_Curiosity_Nano_Target_MCU (J100.2), PIC18F16Q20_Curiosity_Nano_Debugger (R218.1 U206.22)
~{VOFF}: PIC18F16Q20_Curiosity_Nano_Target_MCU (J100.29), PIC18F16Q20_Curiosity_Nano_Debugger (U206.20)

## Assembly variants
Default Assembly: not fitted J107 J108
